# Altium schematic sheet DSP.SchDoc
size A4
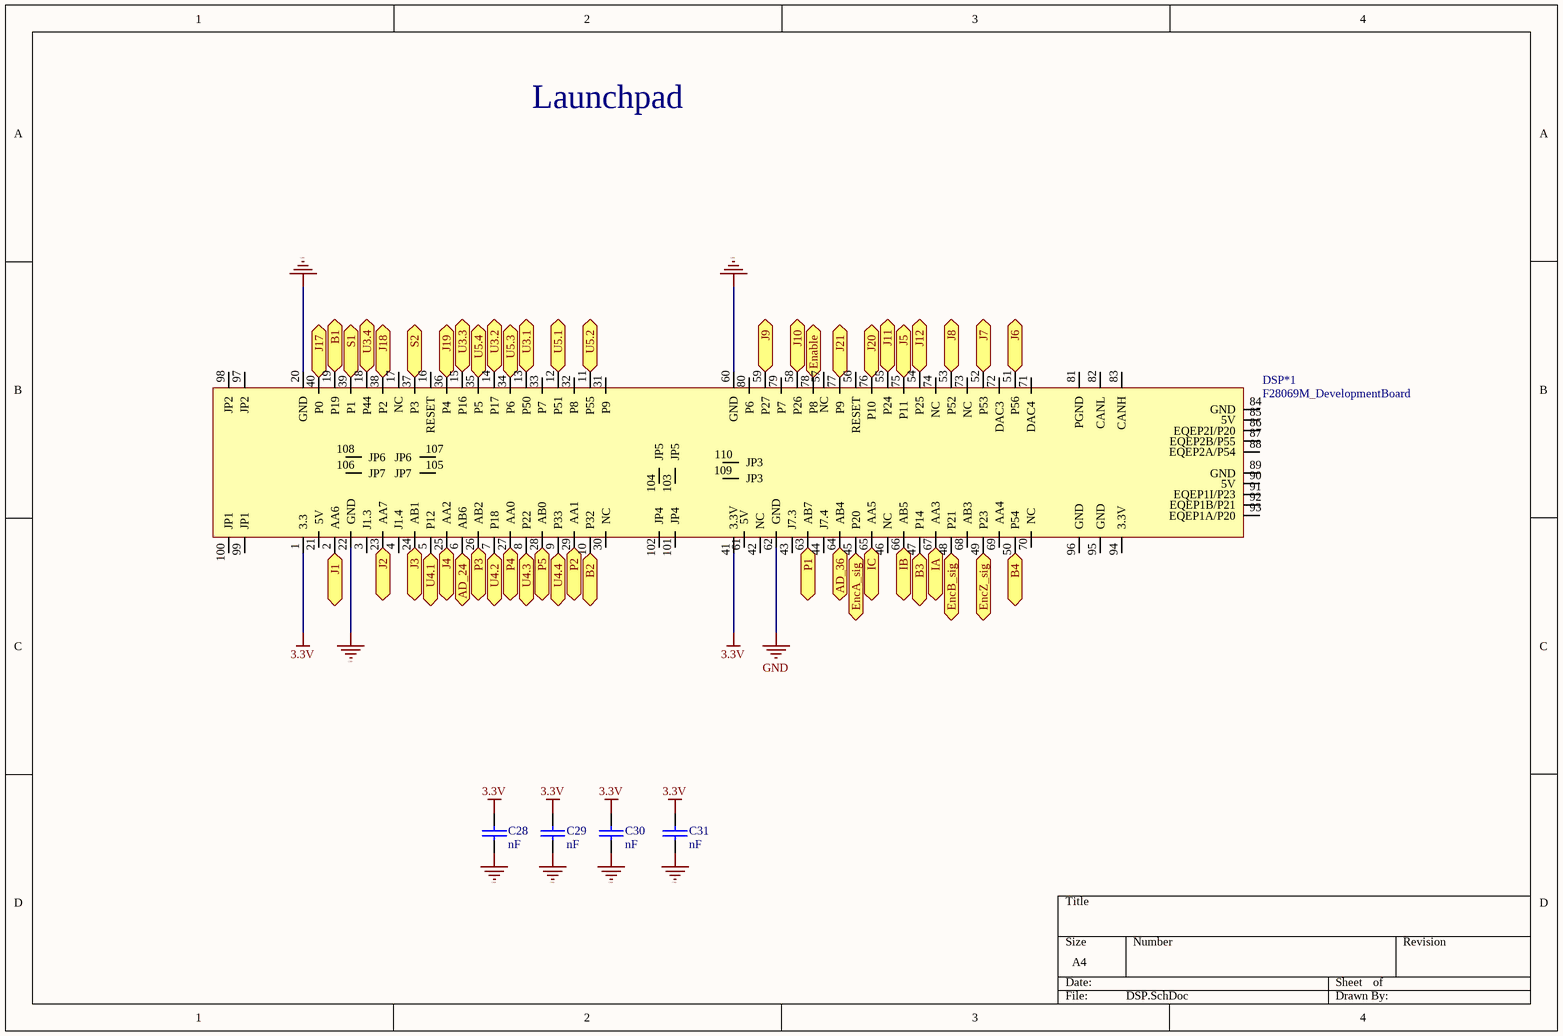
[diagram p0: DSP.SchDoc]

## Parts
C28  nF  [1206]
C29  nF  [1206]
C30  nF  [1206]
C31  nF  [1206]
DSP*1  F28069M_DevelopmentBoard  [F28069M_DevelopmentBoardDOWN]

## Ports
AD_24, AD_36, B1, B2, B3, B4, Enable, EncA_sig, EncB_sig, EncZ_sig, IA, IB, IC, J1, J2, J3, J4, J5, J6, J7, J8, J9, J10, J11, J12, J17, J18, J19, J20, J21, P1, P2, P3, P4, P5, S1, S2, U3.1, U3.2, U3.3, U3.4, U4.1, U4.2, U4.3, U4.4, U5.1, U5.2, U5.3, U5.4

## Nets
3.3V: C28.1 C29.1 C30.1 C31.1 DSP*1.1(3.3) DSP*1.41(3.3V)
GND: C28.2 C29.2 C30.2 C31.2 DSP*1.20(GND) DSP*1.22(GND) DSP*1.60(GND) DSP*1.62(GND)
AD_24: DSP*1.6(AB6) ; port AD_24
AD_36: DSP*1.64(AB4) ; port AD_36
B1: DSP*1.19(P19) ; port B1
B2: DSP*1.10(P32) ; port B2
B3: DSP*1.47(P14) ; port B3
B4: DSP*1.50(P54) ; port B4
Enable: DSP*1.78(P8) ; port Enable
EncA_sig: DSP*1.45(P20) ; port EncA_sig
EncB_sig: DSP*1.48(P21) ; port EncB_sig
EncZ_sig: DSP*1.49(P23) ; port EncZ_sig
IA: DSP*1.67(AA3) ; port IA
IB: DSP*1.66(AB5) ; port IB
IC: DSP*1.65(AA5) ; port IC
J1: DSP*1.2(AA6) ; port J1
J2: DSP*1.23(AA7) ; port J2
J3: DSP*1.24(AB1) ; port J3
J4: DSP*1.25(AA2) ; port J4
J5: DSP*1.75(P11) ; port J5
J6: DSP*1.51(P56) ; port J6
J7: DSP*1.52(P53) ; port J7
J8: DSP*1.53(P52) ; port J8
J9: DSP*1.59(P27) ; port J9
J10: DSP*1.58(P26) ; port J10
J11: DSP*1.55(P24) ; port J11
J12: DSP*1.54(P25) ; port J12
J17: DSP*1.40(P0) ; port J17
J18: DSP*1.38(P2) ; port J18
J19: DSP*1.36(P4) ; port J19
J20: DSP*1.76(P10) ; port J20
J21: DSP*1.77(P9) ; port J21
P1: DSP*1.63(AB7) ; port P1
P2: DSP*1.29(AA1) ; port P2
P3: DSP*1.26(AB2) ; port P3
P4: DSP*1.27(AA0) ; port P4
P5: DSP*1.28(AB0) ; port P5
S1: DSP*1.39(P1) ; port S1
S2: DSP*1.37(P3) ; port S2
U3.1: DSP*1.13(P50) ; port U3.1
U3.2: DSP*1.14(P17) ; port U3.2
U3.3: DSP*1.15(P16) ; port U3.3
U3.4: DSP*1.18(P44) ; port U3.4
U4.1: DSP*1.5(P12) ; port U4.1
U4.2: DSP*1.7(P18) ; port U4.2
U4.3: DSP*1.8(P22) ; port U4.3
U4.4: DSP*1.9(P33) ; port U4.4
U5.1: DSP*1.12(P51) ; port U5.1
U5.2: DSP*1.11(P55) ; port U5.2
U5.3: DSP*1.34(P6) ; port U5.3
U5.4: DSP*1.35(P5) ; port U5.4

Not connected (* = marked no-connect by the designer): DSP*1 3(J1.3) 4(J1.4) 16(RESET) 17(NC) 21(5V) 30(NC) 31(P9) 32(P8) 33(P7) 42(NC) 43(J7.3) 44(J7.4) 46(NC) 56(RESET) 57(NC) 61(5V) 68(AB3) 69(AA4) 70(NC) 71(DAC4) 72(DAC3) 73(NC) 74(NC) 79(P7) 80(P6) 81(PGND) 82(CANL) 83(CANH) 84(GND) 85(5V) 86(EQEP2I/P20) 87(EQEP2B/P55) 88(EQEP2A/P54) 89(GND) 90(5V) 91(EQEP1I/P23) 92(EQEP1B/P21) 93(EQEP1A/P20) 94(3.3V) 95(GND) 96(GND) 97(JP2) 98(JP2) 99(JP1) 100(JP1) 101(JP4) 102(JP4) 103(JP5) 104(JP5) 105(JP7) 106(JP7) 107(JP6) 108(JP6) 109(JP3) 110(JP3)

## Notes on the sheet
- Launchpad

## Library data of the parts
C28-C31 = Condensador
